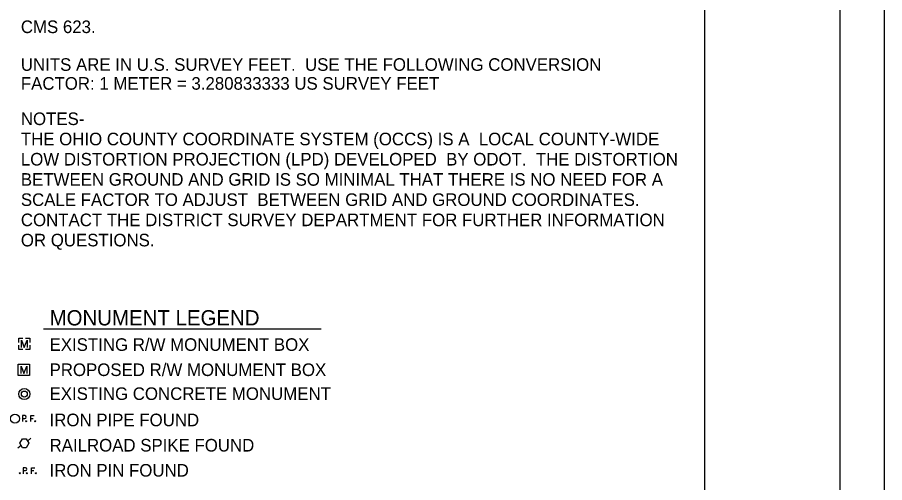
# Model space of a CAD drawing. Extents: x -4.7 to 34, y -3.1 to 22.
# Drawn here: x 24.35 to 34, y 5.39 to 10.57 of the extents above; entities that cross this region are included whole.
import ezdxf

# ---------------------------------------------------------------- set-up
doc = ezdxf.new("R2010")
doc.units = 0
for name, color, linetype in [('SC_Scratch2', 7, 'Continuous'), ('SH_Border', 7, 'Continuous'), ('SH_Cut_Line', 7, 'Continuous')]:
    doc.layers.add(name, color=color, linetype=linetype)

msp = doc.modelspace()

# ---------------------------------------------------------------- linework, layer by layer
at = {"layer": 'SC_Scratch2'}
for p, q in [((24.6376, 7.1047), (27.7303, 7.1047)), ((24.4256, 6.9383), (24.4256, 6.9383)), ((24.421, 6.6479), (24.421, 6.6479)), ((24.4048, 6.1069), (24.4315, 6.1069)), ((24.4985, 6.0721), (24.4985, 6.1388)), ((24.4985, 6.1388), (24.5368, 6.1388)), ((24.4985, 6.1064), (24.5258, 6.1064)), ((24.3921, 5.8064), (24.3521, 5.7765)), ((24.4993, 5.8864), (24.4592, 5.8564)), ((24.4122, 5.5278), (24.4389, 5.5278)), ((24.5058, 5.493), (24.5058, 5.5597)), ((24.5058, 5.5597), (24.5442, 5.5597)), ((24.5058, 5.5273), (24.5332, 5.5273))]:
    msp.add_line(p, q, dxfattribs=at)
for points in [[(24.3631, 6.9541), (24.3631, 7.0009), (24.41, 7.0009)], [(24.3948, 6.8966), (24.3948, 6.98), (24.4256, 6.8966), (24.4565, 6.98), (24.4565, 6.8966)], [(24.4405, 7.0009), (24.4882, 7.0009), (24.4882, 6.9541)], [(24.41, 6.8758), (24.3631, 6.8758), (24.3631, 6.9226)], [(24.4882, 6.9226), (24.4882, 6.8758), (24.4405, 6.8758)], [(24.3585, 6.7104), (24.4836, 6.7104), (24.4836, 6.5854), (24.3585, 6.5854), (24.3585, 6.7104)], [(24.3901, 6.6062), (24.3901, 6.6895), (24.421, 6.6062), (24.4518, 6.6895), (24.4518, 6.6062)], [(24.4315, 6.1388), (24.4048, 6.1388), (24.4048, 6.0721)], [(24.4389, 5.5597), (24.4122, 5.5597), (24.4122, 5.493)]]:
    msp.add_lwpolyline(points, dxfattribs=at)
msp.add_lwpolyline([(24.4069, 5.8814), (24.4444, 5.8814), (24.474, 5.8314), (24.4444, 5.7814), (24.4069, 5.7814), (24.3773, 5.8314)], close=True, dxfattribs=at)
for centre, radius in [((24.4257, 6.3792), 0.0625), ((24.4257, 6.3792), 0.0333), ((24.3215, 6.1055), 0.05), ((24.445, 6.0767), 0.00583), ((24.5466, 6.0767), 0.00583), ((24.3757, 5.4976), 0.00583), ((24.4523, 5.4976), 0.00583), ((24.554, 5.4976), 0.00583)]:
    msp.add_circle(centre, radius, dxfattribs=at)
for centre in [(24.429, 6.1229), (24.4364, 5.5437)]:
    msp.add_arc(centre, 0.0162, 278.88026, 81.11974, dxfattribs=at)
at = {"layer": 'SH_Border'}
msp.add_line((32, 0.5), (32, 21.5), dxfattribs=at)
msp.add_lwpolyline([(1.5, 21.5), (33.5, 21.5), (33.5, 0.5), (1.5, 0.5)], close=True, dxfattribs=at)
at = {"layer": 'SH_Cut_Line'}
msp.add_lwpolyline([(0, 0), (34, 0), (34, 22), (0, 22)], close=True, dxfattribs=at)

# ---------------------------------------------------------------- texts
at = {"layer": 'SC_Scratch2'}
for s, height, p in [('CMS 623.', 0.14, (24.3871, 10.3954)), ('UNITS ARE IN U.S. SURVEY FEET.  USE THE FOLLOWING CONVERSION', 0.14, (24.3871, 9.9754)), ('FACTOR: 1 METER = 3.280833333 US SURVEY FEET', 0.14, (24.3871, 9.7654)), ('NOTES-', 0.14, (24.3871, 9.372)), ('THE OHIO COUNTY COORDINATE SYSTEM (OCCS) IS A  LOCAL COUNTY-WIDE', 0.14, (24.3871, 9.147)), ('LOW DISTORTION PROJECTION (LPD) DEVELOPED  BY ODOT.  THE DISTORTION', 0.14, (24.3871, 8.922)), ('BETWEEN GROUND AND GRID IS SO MINIMAL THAT THERE IS NO NEED FOR A', 0.14, (24.3871, 8.697)), ('SCALE FACTOR TO ADJUST  BETWEEN GRID AND GROUND COORDINATES. ', 0.14, (24.3871, 8.472)), ('CONTACT THE DISTRICT SURVEY DEPARTMENT FOR FURTHER INFORMATION', 0.14, (24.3871, 8.247)), ('OR QUESTIONS.', 0.14, (24.3871, 8.022)), ('MONUMENT LEGEND', 0.17, (24.7067, 7.1426)), ('EXISTING R/W MONUMENT BOX', 0.14, (24.7067, 6.8596)), ('PROPOSED R/W MONUMENT BOX', 0.14, (24.7067, 6.5796)), ('EXISTING CONCRETE MONUMENT', 0.14, (24.7067, 6.3133)), ('IRON PIPE FOUND', 0.14, (24.7067, 6.021)), ('RAILROAD SPIKE FOUND', 0.14, (24.7067, 5.7396)), ('IRON PIN FOUND', 0.14, (24.7067, 5.4605))]:
    msp.add_text(s, height=height, dxfattribs=at).set_placement(p)

doc.saveas('drawing.dxf')
